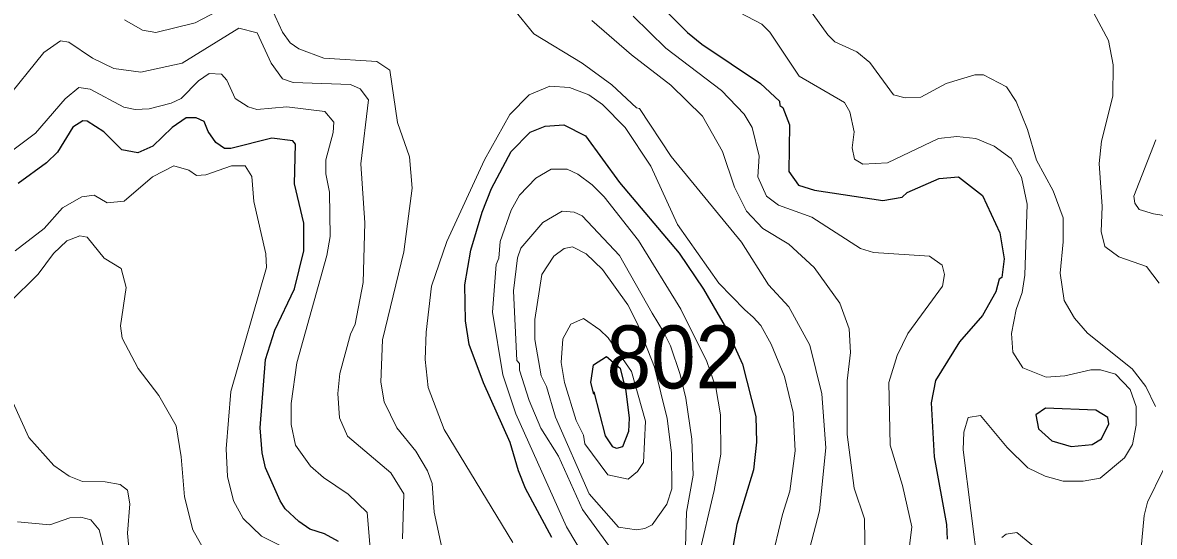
# Model space of a CAD drawing. Extents: x 673.3 to 698.5, y 6984.3 to 7012.3.
# Drawn here: x 687.432 to 688.869, y 6995.971 to 6996.624 of the extents above; entities that cross this region are included whole.
import ezdxf

# ---------------------------------------------------------------- set-up
doc = ezdxf.new("R2010")
doc.units = 0
doc.header["$LTSCALE"] = 0.032
doc.layers.add('1', color=7, linetype='Continuous', lineweight=25)
doc.layers.add('2', color=7, linetype='Continuous', lineweight=13)
doc.layers.add('21', color=7, linetype='Continuous')

msp = doc.modelspace()

# ---------------------------------------------------------------- linework, layer by layer
at = {"layer": '1'}
for points in [[(688.2352, 6996.6522), (688.2762, 6996.6112), (688.2943, 6996.5963), (688.3688, 6996.5463), (688.3933, 6996.5241), (688.3935, 6996.5187), (688.3975, 6996.5158), (688.4057, 6996.494), (688.4049, 6996.4348), (688.4171, 6996.4173), (688.4377, 6996.4109), (688.5244, 6996.398), (688.549, 6996.4021), (688.5554, 6996.408), (688.5957, 6996.4257), (688.6203, 6996.428), (688.6509, 6996.4042), (688.6729, 6996.3569), (688.6784, 6996.3238), (688.6753, 6996.2999), (688.6722, 6996.2978), (688.668, 6996.282), (688.6509, 6996.2516), (688.6217, 6996.2182), (688.5914, 6996.169), (688.5857, 6996.1408), (688.5897, 6996.0721), (688.6052, 6995.9861), (688.606, 6995.9676)], [(687.833, 6995.9646), (687.8152, 6995.9744), (687.7967, 6995.9805), (687.7826, 6995.99), (687.7656, 6996.0061), (687.7589, 6996.0163), (687.7406, 6996.0584), (687.7362, 6996.0773), (687.7339, 6996.109), (687.7404, 6996.1959), (687.7523, 6996.2331), (687.7773, 6996.2856), (687.7892, 6996.3341), (687.7892, 6996.3689), (687.7771, 6996.4188), (687.7786, 6996.4693), (687.775, 6996.4736), (687.7485, 6996.4769), (687.6963, 6996.4639), (687.6885, 6996.4639), (687.6776, 6996.4714), (687.6677, 6996.4853), (687.6626, 6996.4981), (687.6526, 6996.5028), (687.6397, 6996.5029), (687.622, 6996.4905), (687.5976, 6996.4668), (687.5785, 6996.4583), (687.558, 6996.4623), (687.535, 6996.485), (687.5142, 6996.4987), (687.5085, 6996.4989), (687.4959, 6996.4912), (687.4764, 6996.4591), (687.4624, 6996.4458), (687.4265, 6996.4195)], [(688.1042, 6995.9698), (688.0708, 6996.0319), (688.0616, 6996.0543), (688.0513, 6996.0903), (688.0173, 6996.1663), (687.9991, 6996.2151), (687.9944, 6996.2451), (687.9937, 6996.2907), (688.0014, 6996.3348), (688.0155, 6996.3829), (688.0273, 6996.4132), (688.0524, 6996.46), (688.0764, 6996.4848), (688.0955, 6996.4923), (688.1193, 6996.4939), (688.1468, 6996.4799), (688.1898, 6996.4207), (688.2658, 6996.3309), (688.2967, 6996.2852), (688.326, 6996.2348), (688.3463, 6996.1899), (688.3629, 6996.1233), (688.3639, 6996.0907), (688.36, 6996.0558), (688.339, 6995.9861), (688.3266, 6995.9158)], [(688.1575, 6996.152), (688.1536, 6996.1665), (688.157, 6996.1889), (688.1735, 6996.1995), (688.191, 6996.185), (688.1979, 6996.1557), (688.2021, 6996.1214), (688.2013, 6996.1045), (688.1936, 6996.0851), (688.1863, 6996.0829), (688.1813, 6996.0849), (688.1723, 6996.099), (688.1576, 6996.1548)]]:
    msp.add_lwpolyline(points, dxfattribs=at)
msp.add_lwpolyline([(688.7636, 6996.0852), (688.7902, 6996.0878), (688.8021, 6996.095), (688.8111, 6996.1142), (688.8099, 6996.1222), (688.7949, 6996.1316), (688.7309, 6996.134), (688.7186, 6996.1256), (688.722, 6996.1079), (688.739, 6996.0925)], close=True, dxfattribs=at)
at = {"layer": '2'}
for points in [[(687.5614, 6996.6273), (687.5842, 6996.6144), (687.6012, 6996.6113), (687.651, 6996.6236), (687.7088, 6996.6541)], [(687.7434, 6996.6526), (687.7619, 6996.6116), (687.7719, 6996.5983), (687.7829, 6996.5903), (687.8146, 6996.5787), (687.882, 6996.5746), (687.8983, 6996.5632), (687.9081, 6996.4969), (687.9235, 6996.4533), (687.9269, 6996.4137), (687.9162, 6996.3328), (687.8892, 6996.221), (687.887, 6996.1671), (687.891, 6996.142), (687.9074, 6996.109), (687.9315, 6996.0793), (687.9462, 6996.0545)], [(688.6458, 6995.9269), (688.6264, 6996.0812), (688.6272, 6996.1035), (688.6328, 6996.1223), (688.6485, 6996.1248), (688.682, 6996.0841), (688.7086, 6996.0584), (688.7303, 6996.0478), (688.7531, 6996.0412), (688.7786, 6996.0413), (688.8004, 6996.0453), (688.8311, 6996.0708), (688.8412, 6996.0877), (688.8462, 6996.1126), (688.8462, 6996.136), (688.8383, 6996.1579), (688.8198, 6996.1773), (688.8006, 6996.1828), (688.7886, 6996.1828), (688.7556, 6996.1753), (688.7317, 6996.1733), (688.7022, 6996.1853), (688.6893, 6996.2051), (688.6875, 6996.2289), (688.6935, 6996.2595), (688.7013, 6996.281), (688.7045, 6996.3031), (688.7077, 6996.393), (688.7003, 6996.4275), (688.6871, 6996.4511), (688.6657, 6996.4668), (688.6423, 6996.4765), (688.6182, 6996.4793), (688.5951, 6996.4767), (688.5301, 6996.4455), (688.4989, 6996.4442), (688.4882, 6996.4503), (688.4854, 6996.4648), (688.4878, 6996.4849), (688.4824, 6996.5104), (688.4756, 6996.5225), (688.4183, 6996.5556), (688.381, 6996.6116), (688.3706, 6996.6218), (688.2964, 6996.6613)], [(688.422, 6995.9193), (688.4439, 6996.0037), (688.4521, 6996.0836), (688.447, 6996.1522), (688.4316, 6996.2141), (688.4048, 6996.2627), (688.3792, 6996.2906), (688.3447, 6996.345), (688.2555, 6996.4536), (688.2153, 6996.5147), (688.2117, 6996.5154), (688.1804, 6996.5449), (688.1424, 6996.5723), (688.081, 6996.6095), (688.057, 6996.6392)], [(688.425, 6996.6494), (688.4543, 6996.6083), (688.4635, 6996.5996), (688.4912, 6996.5868), (688.508, 6996.5733), (688.5379, 6996.5322), (688.5528, 6996.5282), (688.5725, 6996.5291), (688.6046, 6996.5465), (688.641, 6996.5575), (688.6522, 6996.5576), (688.6815, 6996.5422), (688.6938, 6996.5236), (688.7081, 6996.4881), (688.7195, 6996.449), (688.7406, 6996.4103), (688.7533, 6996.3758), (688.7534, 6996.3455), (688.7493, 6996.3055), (688.7547, 6996.2708), (688.7678, 6996.2485), (688.7843, 6996.2294), (688.8411, 6996.1839), (688.8584, 6996.1617), (688.8704, 6996.1363)], [(688.1548, 6996.6267), (688.2053, 6996.5827), (688.2553, 6996.5442), (688.2954, 6996.5049), (688.3209, 6996.4599), (688.3359, 6996.4148), (688.3513, 6996.3843), (688.3721, 6996.3624), (688.4051, 6996.3423), (688.4372, 6996.3127)], [(688.2072, 6996.6322), (688.2489, 6996.5914), (688.3196, 6996.5377), (688.3483, 6996.5075), (688.3585, 6996.4904), (688.3673, 6996.454), (688.3658, 6996.4281), (688.3767, 6996.4033), (688.392, 6996.3918), (688.4342, 6996.3767), (688.4961, 6996.3369), (688.5126, 6996.3319), (688.5837, 6996.327), (688.5995, 6996.3156), (688.6028, 6996.3039), (688.6002, 6996.2889), (688.556, 6996.2287), (688.5426, 6996.201), (688.5319, 6996.1666), (688.5336, 6996.0869), (688.5491, 6996.0357), (688.5612, 6995.9832), (688.553, 6995.9177)], [(688.8753, 6996.2929), (688.859, 6996.3141), (688.8241, 6996.3263), (688.806, 6996.3395), (688.8015, 6996.3585), (688.803, 6996.3904), (688.7991, 6996.4447), (688.802, 6996.4733), (688.8162, 6996.5305), (688.817, 6996.5702), (688.8107, 6996.6009), (688.7923, 6996.636)], [(687.9146, 6995.9679), (687.9162, 6996.0254), (687.8996, 6996.052), (687.8444, 6996.0983), (687.8343, 6996.1216), (687.8323, 6996.1525), (687.8347, 6996.178), (687.8486, 6996.2282), (687.8544, 6996.2406), (687.8643, 6996.2937), (687.8665, 6996.3693), (687.8617, 6996.4446), (687.8713, 6996.5259), (687.8606, 6996.5397), (687.8483, 6996.5452), (687.7757, 6996.5476), (687.7621, 6996.5522), (687.7475, 6996.5725), (687.7298, 6996.6109), (687.7067, 6996.6167), (687.6346, 6996.5721), (687.5823, 6996.5608), (687.5481, 6996.5657), (687.5207, 6996.5788), (687.4907, 6996.5988), (687.48, 6996.6006), (687.4592, 6996.5858), (687.4078, 6996.5223)], [(687.8736, 6995.951), (687.8696, 6996.0013), (687.8456, 6996.0247), (687.8141, 6996.0459), (687.7978, 6996.0603), (687.7786, 6996.087), (687.7729, 6996.1132), (687.7729, 6996.1399), (687.7804, 6996.1917), (687.8184, 6996.3279), (687.8225, 6996.352), (687.8217, 6996.4084), (687.8169, 6996.4318), (687.8169, 6996.4494), (687.8266, 6996.4842), (687.8274, 6996.4975), (687.8159, 6996.5109), (687.7677, 6996.5167), (687.7293, 6996.5136), (687.7185, 6996.517), (687.7021, 6996.5275), (687.6915, 6996.5507), (687.6848, 6996.5582), (687.6689, 6996.5591), (687.6554, 6996.5499), (687.6334, 6996.5276), (687.6208, 6996.5214), (687.5926, 6996.5142), (687.5748, 6996.5136), (687.5605, 6996.5164), (687.5178, 6996.5392), (687.5036, 6996.5412), (687.4859, 6996.527), (687.4485, 6996.4832), (687.4181, 6996.4607)], [(688.0545, 6995.9633), (687.9673, 6996.1069), (687.9472, 6996.1602), (687.9431, 6996.1957), (687.9443, 6996.2307), (687.9513, 6996.2891), (687.9706, 6996.3456), (688.0185, 6996.4495), (688.0508, 6996.5069), (688.0751, 6996.5322), (688.1017, 6996.543), (688.1266, 6996.5412), (688.1511, 6996.5321), (688.1682, 6996.5197), (688.1973, 6996.4905), (688.2296, 6996.4413), (688.2638, 6996.3672), (688.3162, 6996.2929), (688.3489, 6996.2591), (688.3598, 6996.2498), (688.3696, 6996.2392), (688.3824, 6996.2155), (688.3995, 6996.1741), (688.4106, 6996.1285), (688.4129, 6996.0797), (688.4064, 6996.0285), (688.3968, 6995.9991), (688.382, 6995.937)], [(688.8708, 6996.475), (688.843, 6996.4034), (688.8443, 6996.3946), (688.85, 6996.3866), (688.8678, 6996.3808), (688.8978, 6996.3761)], [(687.4225, 6996.3339), (687.4596, 6996.3624), (687.4827, 6996.3887), (687.5071, 6996.4027), (687.5228, 6996.4044), (687.5395, 6996.3947), (687.5609, 6996.3971), (687.5969, 6996.428), (687.6239, 6996.4418), (687.6432, 6996.4362), (687.6528, 6996.4297), (687.6649, 6996.4303), (687.6974, 6996.4417), (687.7147, 6996.4418), (687.7233, 6996.4282), (687.7256, 6996.3966), (687.741, 6996.3301), (687.7419, 6996.3129), (687.6964, 6996.1552), (687.6907, 6996.0824), (687.6923, 6996.0471), (687.6997, 6996.0162), (687.7122, 6995.9937), (687.7356, 6995.9716), (687.8086, 6995.9344)], [(688.2902, 6995.9446), (688.3103, 6996.0296), (688.3186, 6996.0757), (688.3182, 6996.1257), (688.3121, 6996.1602), (688.3008, 6996.1931), (688.2679, 6996.2597), (688.2142, 6996.347), (688.1705, 6996.4026), (688.1552, 6996.4178), (688.1369, 6996.4312), (688.1236, 6996.4375), (688.1033, 6996.4378), (688.0837, 6996.4263), (688.0628, 6996.4044), (688.0526, 6996.3856), (688.0383, 6996.3458), (688.0367, 6996.3247), (688.0335, 6996.3164), (688.0287, 6996.2558), (688.0417, 6996.1762), (688.0583, 6996.1268), (688.1228, 6995.9832), (688.1465, 6995.9436)], [(688.273, 6995.9278), (688.2749, 6996.0017), (688.2835, 6996.0487), (688.2819, 6996.0947), (688.2743, 6996.1466), (688.2669, 6996.177), (688.2548, 6996.2131), (688.2459, 6996.231), (688.2316, 6996.2546), (688.1898, 6996.3278), (688.1427, 6996.3782), (688.1325, 6996.3832), (688.1172, 6996.3841), (688.0925, 6996.3698), (688.0648, 6996.3373), (688.0604, 6996.3251), (688.0555, 6996.2832), (688.0596, 6996.1946), (688.0628, 6996.1907), (688.063, 6996.1821), (688.0751, 6996.1438), (688.0902, 6996.1086), (688.1123, 6996.0732), (688.1428, 6996.0052), (688.176, 6995.9598)], [(687.6737, 6995.9343), (687.6482, 6995.9796), (687.6378, 6996.0213), (687.6336, 6996.0724), (687.6271, 6996.1117), (687.6051, 6996.1503), (687.579, 6996.1845), (687.5585, 6996.223), (687.5563, 6996.2386), (687.5636, 6996.2872), (687.5573, 6996.3116), (687.5358, 6996.3247), (687.5141, 6996.3513), (687.5049, 6996.3531), (687.4884, 6996.3464), (687.4713, 6996.3303)], [(687.4713, 6996.3303), (687.452, 6996.3042), (687.4149, 6996.2678)], [(688.4372, 6996.3127), (688.4699, 6996.2676), (688.4815, 6996.2347), (688.4831, 6996.2046), (688.479, 6996.1689), (688.479, 6996.1004), (688.488, 6996.0325), (688.501, 6995.9933), (688.5017, 6995.9383)], [(687.4197, 6996.1416), (687.4399, 6996.0967), (687.4719, 6996.0612), (687.4911, 6996.0477), (687.5081, 6996.0407), (687.5371, 6996.0404), (687.556, 6996.0372), (687.5652, 6996.0297), (687.5684, 6996.0126), (687.5652, 6995.9752), (687.5685, 6995.9383)], [(687.9462, 6996.0545), (687.9519, 6996.0382), (687.9545, 6996.0018), (687.9661, 6995.9488)], [(688.8804, 6996.0553), (688.8603, 6996.0145), (688.8561, 6995.9975), (688.852, 6995.9523)], [(687.5456, 6995.9145), (687.5291, 6995.9796), (687.5188, 6995.9922), (687.5058, 6995.9955), (687.4922, 6995.9946), (687.4667, 6995.9859), (687.4257, 6995.9897)], [(688.7346, 6995.9431), (688.6944, 6995.976), (688.6808, 6995.9738), (688.6756, 6995.9698)]]:
    msp.add_lwpolyline(points, dxfattribs=at)
for points in [[(688.1682, 6996.3103), (688.1478, 6996.3302), (688.1301, 6996.3391), (688.1198, 6996.3368), (688.1067, 6996.327), (688.0913, 6996.304), (688.0824, 6996.2467), (688.0824, 6996.2212), (688.0907, 6996.1752), (688.0971, 6996.1615), (688.1087, 6996.1227), (688.1514, 6996.0252), (688.1889, 6995.9828), (688.2116, 6995.9794), (688.2223, 6995.981), (688.2314, 6995.986), (688.2502, 6996.0122), (688.2566, 6996.0315), (688.2558, 6996.0774), (688.2504, 6996.1211), (688.2343, 6996.186), (688.2127, 6996.2413), (688.2007, 6996.2655)], [(688.118, 6996.2221), (688.128, 6996.2407), (688.1442, 6996.2479), (688.1652, 6996.2335), (688.1754, 6996.2234), (688.2054, 6996.1806), (688.2231, 6996.1177), (688.2206, 6996.0648), (688.2128, 6996.0536), (688.2011, 6996.0438), (688.1753, 6996.0494), (688.1459, 6996.0888), (688.1441, 6996.0999), (688.1348, 6996.1185), (688.1202, 6996.1667), (688.1161, 6996.1921)]]:
    msp.add_lwpolyline(points, close=True, dxfattribs=at)

# ---------------------------------------------------------------- texts
at = {"layer": '21', "width": 0.95}
msp.add_text('802', height=0.08, dxfattribs=at).set_placement((688.1736, 6996.1591))

doc.saveas('drawing.dxf')
